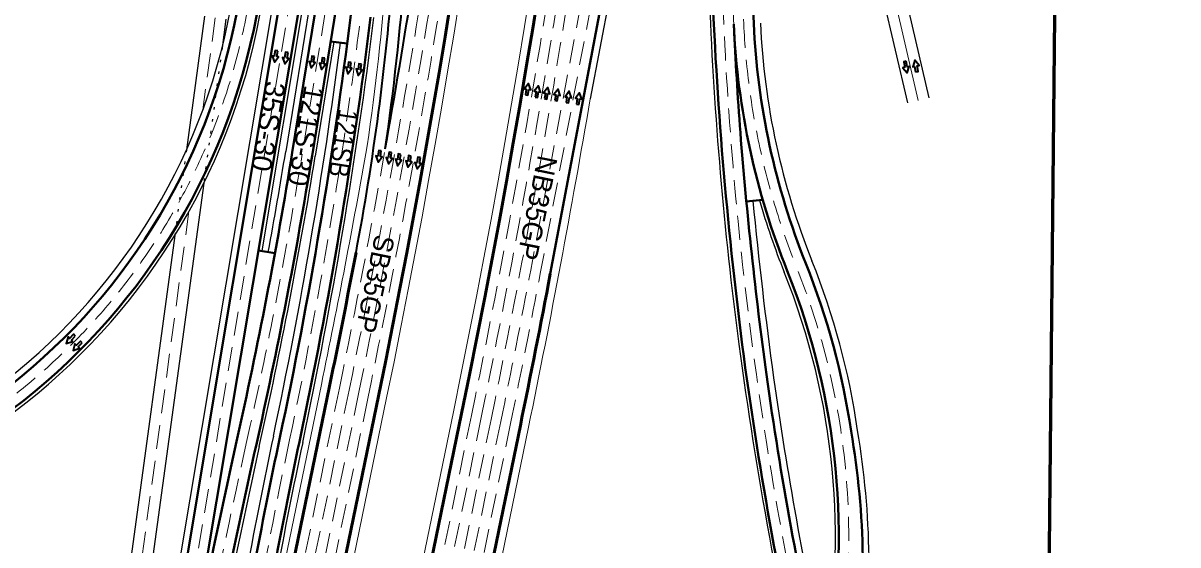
# Model space of a CAD drawing. Extents: x 2329387 to 2347382, y 6951580 to 6987999.
# Drawn here: x 2331366 to 2332753, y 6961173 to 6961800 of the extents above; entities that cross this region are included whole.
import ezdxf

# ---------------------------------------------------------------- set-up
doc = ezdxf.new("R2010")
doc.units = 0
doc.header["$LTSCALE"] = 9.6
doc.linetypes.add('DOTTED', pattern=[1.5, 0.3, -1.2])
doc.linetypes.add('MEDIUM_DASHED', pattern=[4.5, 3, -1.5])
for name, color, linetype, lineweight in [('26', 7, 'Continuous', 53), ('27', 7, 'Continuous', 40), ('28', 7, 'Continuous', 25), ('29', 7, 'DOTTED', 35), ('41', 7, 'Continuous', 35), ('50', 7, 'MEDIUM_DASHED', 13), ('62', 7, 'Continuous', 60), ('63', 7, 'Continuous', 25)]:
    doc.layers.add(name, color=color, linetype=linetype, lineweight=lineweight)
doc.layers.add('40', color=7, linetype='Continuous')

msp = doc.modelspace()

# ---------------------------------------------------------------- linework, layer by layer
at = {"layer": '26', "lineweight": 13}
for p, q in [((2331724.458, 6961366.169), (2331675.26, 6961127.125)), ((2331802.815, 6961350.042), (2331719.775, 6960946.564)), ((2331883.115, 6961333.431), (2331797.054, 6960915.276)), ((2331973.227, 6961314.885), (2331928.251, 6961096.357))]:
    msp.add_line(p, q, dxfattribs=at)
at = {"layer": '26'}
for p, q in [((2331734.252, 6961364.153), (2331685.095, 6961125.305)), ((2331734.252, 6961364.153), (2331685.095, 6961125.305)), ((2331793.021, 6961352.058), (2331710.29, 6960950.086)), ((2331892.91, 6961331.415), (2331806.417, 6960911.164)), ((2331963.432, 6961316.901), (2331918.456, 6961098.373))]:
    msp.add_line(p, q, dxfattribs=at)
for centre, radius, end in [((2320619.05, 6963651.709), 11510.156, 3.41668), ((2321018.843, 6963569.511), 11000, 2.99621), ((2321018.843, 6963569.511), 10940, 349.22683), ((2320619.05, 6963651.709), 11582.156, 349.28886)]:
    msp.add_arc(centre, radius, 348.37024, end, dxfattribs=at)
at = {"layer": '26', "lineweight": 13}
for centre, radius, end in [((2320619.05, 6963651.709), 11500.156, 3.35435), ((2321018.843, 6963569.511), 11010, 3.10741), ((2320619.05, 6963651.709), 11592.156, 350.35319), ((2321018.843, 6963569.511), 10930, 349.89956)]:
    msp.add_arc(centre, radius, 348.37024, end, dxfattribs=at)
at = {"layer": '27', "lineweight": 25}
for p, q in [((2331820.221, 6962498.609), (2331681.587, 6961645.951)), ((2331775.493, 6962479.35), (2331530.014, 6961010.115)), ((2331811.001, 6962473.417), (2331652.783, 6961526.455)), ((2332147.959, 6962241.392), (2332047.286, 6961709.162)), ((2331739.453, 6961777.528), (2331717.12, 6961640.174))]:
    msp.add_line(p, q, dxfattribs=at)
at = {"layer": '27'}
for p, q in [((2331828.117, 6962497.325), (2331689.483, 6961644.667)), ((2331783.384, 6962478.032), (2331537.705, 6961007.603)), ((2331807.056, 6962474.077), (2331560.779, 6961000.065)), ((2331819.966, 6962297.645), (2331713.172, 6961640.816)), ((2332140.099, 6962242.879), (2331999.406, 6961499.077)), ((2331735.484, 6961778.042), (2331755.318, 6961775.472)), ((2332254.609, 6961587.81), (2332234.696, 6961585.943)), ((2331668.564, 6961523.818), (2331648.838, 6961527.114))]:
    msp.add_line(p, q, dxfattribs=at)
for centre, radius, start, end in [((2339406.145, 6959556.474), 7976, 170.51466, 170.51466), ((2337955.315, 6962060.73), 5717.578, 174.34987, 182.61584), ((2330886.127, 6961953.624), 750.001, 266.08609, 350.71584), ((2330886.127, 6961953.624), 774.001, 266.08608, 350.71582), ((2337105.762, 6962041.019), 4915.948, 182.49984, 187.6536), ((2325828.855, 6962543.331), 5976, 348.01367, 352.95352), ((2325828.855, 6962543.331), 6000, 348.01367, 352.95352), ((2333124.25, 6961840.014), 905.473, 182.61584, 201.88176), ((2336798.354, 6962013.709), 4583.662, 182.68873, 184.31651), ((2333124.25, 6961840.014), 881.473, 182.61584, 201.88176), ((2337308.502, 6962068.63), 5096.522, 184.50052, 187.78871), ((2325767.265, 6962607.563), 5999.987, 347.39024, 350.76507), ((2325767.265, 6962607.563), 6023.987, 347.39024, 350.76507), ((2331488.314, 6961182.977), 857.473, 316.98269, 21.88176), ((2331488.314, 6961182.977), 881.473, 8.27518, 21.88176), ((2336798.354, 6962013.709), 4607.662, 187.82614, 193.20332), ((2336798.354, 6962013.709), 4583.662, 187.97272, 192.59319), ((2331429.011, 6961146.766), 945.765, 351.62744, 9.92921), ((2339406.145, 6959556.474), 7976, 167.39024, 169.57492), ((2339406.145, 6959556.474), 7952, 167.39024, 169.5982), ((2337567.201, 6960051.195), 6023.98, 168.01367, 171.10971), ((2337567.201, 6960051.195), 5999.98, 168.01367, 171.14683)]:
    msp.add_arc(centre, radius, start, end, dxfattribs=at)
at = {"layer": '27', "lineweight": 25}
for centre, radius, start, end in [((2330886.127, 6961953.624), 742.001, 266.08609, 350.71584), ((2330886.127, 6961953.624), 778.001, 266.08608, 350.71189), ((2336798.354, 6962013.709), 4611.662, 182.32731, 187.46451), ((2325828.855, 6962543.331), 6004, 348.01367, 352.95352), ((2333124.25, 6961840.014), 873.473, 182.61584, 201.88176), ((2325828.855, 6962543.331), 5968, 348.01367, 352.61764), ((2325767.265, 6962607.563), 6027.987, 347.39024, 350.76507), ((2325767.265, 6962607.563), 5991.987, 349.59262, 350.76507), ((2337545.513, 6962101.409), 5327.774, 185.54402, 187.84514), ((2333124.25, 6961840.014), 909.473, 196.12452, 201.88176), ((2331488.314, 6961182.977), 889.473, 8.27518, 21.88176), ((2331488.314, 6961182.977), 853.473, 316.98269, 21.88176), ((2337081.285, 6962065.532), 4898.95, 187.63559, 193.12349), ((2336798.354, 6962013.709), 4575.662, 188.03429, 192.35956), ((2337567.201, 6960051.195), 6031.98, 168.01367, 171.0974), ((2331388.291, 6961146.248), 993.984, 351.97584, 9.5406), ((2339406.145, 6959556.474), 7948, 167.39024, 169.60209), ((2337567.201, 6960051.195), 5995.98, 168.01367, 171.15332)]:
    msp.add_arc(centre, radius, start, end, dxfattribs=at)
at = {"layer": '28'}
for p, q in [((2332428.738, 6961704.35), (2332371.919, 6961949.587)), ((2332398.645, 6961949.425), (2332454.067, 6961710.219))]:
    msp.add_line(p, q, dxfattribs=at)
at = {"layer": '28', "lineweight": 13}
msp.add_arc((2328818.901, 6962085.355), 2991.998, 351.68506, 355.72896, dxfattribs=at)
at = {"layer": '29', "linetype": 'Continuous'}
for centre, radius, start, end in [((2321018.843, 6963569.511), 10952, 349.90135, 352.02498), ((2328818.901, 6962085.355), 2999.998, 349.22683, 355.72896), ((2328818.901, 6962085.355), 3013.998, 351.67854, 355.72896)]:
    msp.add_arc(centre, radius, start, end, dxfattribs=at)
at = {"layer": '41'}
for points in [[(2331671.923, 6961766.656), (2331668.961, 6961767.137), (2331667.87, 6961760.418), (2331665.464, 6961760.809), (2331668.04, 6961753.096), (2331672.924, 6961759.597), (2331670.832, 6961759.937)], [(2331684.341, 6961764.683), (2331681.379, 6961765.164), (2331680.288, 6961758.445), (2331677.882, 6961758.836), (2331680.458, 6961751.123), (2331685.342, 6961757.625), (2331683.25, 6961757.964)], [(2331716.082, 6961759.915), (2331713.12, 6961760.396), (2331712.029, 6961753.677), (2331709.623, 6961754.068), (2331712.199, 6961746.355), (2331717.083, 6961752.856), (2331714.991, 6961753.196)], [(2331728.5, 6961757.942), (2331725.538, 6961758.423), (2331724.447, 6961751.704), (2331722.041, 6961752.095), (2331724.617, 6961744.382), (2331729.501, 6961750.884), (2331727.409, 6961751.223)], [(2331760.083, 6961752.885), (2331757.121, 6961753.366), (2331756.03, 6961746.647), (2331753.624, 6961747.038), (2331756.2, 6961739.325), (2331761.084, 6961745.827), (2331758.992, 6961746.166)], [(2331772.501, 6961750.912), (2331769.539, 6961751.393), (2331768.448, 6961744.675), (2331766.042, 6961745.065), (2331768.618, 6961737.352), (2331773.502, 6961743.854), (2331771.41, 6961744.194)], [(2332426.905, 6961754.343), (2332423.961, 6961753.765), (2332425.271, 6961747.086), (2332422.879, 6961746.616), (2332427.973, 6961740.278), (2332430.295, 6961748.071), (2332428.215, 6961747.663)], [(2332438.219, 6961741.44), (2332441.163, 6961742.017), (2332439.853, 6961748.697), (2332442.245, 6961749.166), (2332437.15, 6961755.504), (2332434.828, 6961747.711), (2332436.908, 6961748.119)], [(2331969.402, 6961713.964), (2331972.364, 6961713.483), (2331973.455, 6961720.202), (2331975.861, 6961719.811), (2331973.285, 6961727.524), (2331968.401, 6961721.023), (2331970.493, 6961720.683)], [(2331981.187, 6961711.313), (2331984.149, 6961710.832), (2331985.24, 6961717.55), (2331987.646, 6961717.16), (2331985.07, 6961724.872), (2331980.186, 6961718.371), (2331982.278, 6961718.031)], [(2331992.339, 6961709.395), (2331995.301, 6961708.914), (2331996.392, 6961715.632), (2331998.798, 6961715.242), (2331996.222, 6961722.954), (2331991.338, 6961716.453), (2331993.43, 6961716.113)], [(2332004.757, 6961707.422), (2332007.719, 6961706.941), (2332008.81, 6961713.66), (2332011.216, 6961713.269), (2332008.64, 6961720.982), (2332003.756, 6961714.48), (2332005.848, 6961714.141)], [(2332018.287, 6961704.725), (2332021.249, 6961704.244), (2332022.34, 6961710.962), (2332024.746, 6961710.572), (2332022.17, 6961718.284), (2332017.286, 6961711.783), (2332019.378, 6961711.443)], [(2332030.705, 6961702.752), (2332033.667, 6961702.271), (2332034.758, 6961708.99), (2332037.163, 6961708.599), (2332034.588, 6961716.312), (2332029.704, 6961709.81), (2332031.796, 6961709.47)], [(2331796.341, 6961646.688), (2331793.38, 6961647.169), (2331792.289, 6961640.451), (2331789.883, 6961640.841), (2331792.459, 6961633.129), (2331797.343, 6961639.63), (2331795.25, 6961639.97)], [(2331808.759, 6961644.716), (2331805.797, 6961645.197), (2331804.706, 6961638.478), (2331802.301, 6961638.869), (2331804.876, 6961631.156), (2331809.76, 6961637.657), (2331807.668, 6961637.997)], [(2331819.715, 6961642.451), (2331816.753, 6961642.932), (2331815.662, 6961636.214), (2331813.257, 6961636.604), (2331815.833, 6961628.892), (2331820.717, 6961635.393), (2331818.624, 6961635.733)], [(2331832.133, 6961640.479), (2331829.171, 6961640.96), (2331828.08, 6961634.241), (2331825.674, 6961634.632), (2331828.25, 6961626.919), (2331833.134, 6961633.42), (2331831.042, 6961633.76)], [(2331843.286, 6961638.561), (2331840.324, 6961639.042), (2331839.233, 6961632.323), (2331836.827, 6961632.714), (2331839.403, 6961625.001), (2331844.287, 6961631.502), (2331842.195, 6961631.842)], [(2331428.833, 6961424.295), (2331426.665, 6961426.369), (2331421.959, 6961421.452), (2331420.198, 6961423.137), (2331417.95, 6961415.322), (2331425.659, 6961417.911), (2331424.127, 6961419.377)], [(2331437.107, 6961416.053), (2331434.939, 6961418.128), (2331430.233, 6961413.21), (2331428.472, 6961414.895), (2331426.224, 6961407.081), (2331433.933, 6961409.67), (2331432.401, 6961411.136)]]:
    msp.add_lwpolyline(points, close=True, dxfattribs=at)
at = {"layer": '50'}
for p, q in [((2331839.962, 6962495.399), (2331701.328, 6961642.742)), ((2331795.22, 6962476.054), (2331549.242, 6961003.834)), ((2332116.517, 6962247.339), (2331975.824, 6961503.538)), ((2332128.308, 6962245.109), (2331987.615, 6961501.307)), ((2331757.76, 6961359.315), (2331676.038, 6960962.247)), ((2331746.006, 6961361.734), (2331696.848, 6961122.886)), ((2331769.513, 6961356.896), (2331687.474, 6960958.284)), ((2331780.211, 6961349.347), (2331698.891, 6960954.23)), ((2331904.664, 6961328.996), (2331817.635, 6960906.143)), ((2331916.417, 6961326.577), (2331828.834, 6960901.027)), ((2331928.171, 6961324.158), (2331840.013, 6960895.817)), ((2331939.925, 6961321.739), (2331851.173, 6960890.511)), ((2331951.678, 6961319.32), (2331862.312, 6960885.108))]:
    msp.add_line(p, q, dxfattribs=at)
at = {"layer": '50', "linetype": 'Continuous'}
msp.add_line((2332441.403, 6961707.284), (2332384.584, 6961952.521), dxfattribs=at)
at = {"layer": '50'}
for centre, radius, start, end in [((2320619.05, 6963651.709), 11546.156, 348.37024, 3.62206), ((2320619.05, 6963651.709), 11534.156, 348.37024, 3.55667), ((2320619.05, 6963651.709), 11522.156, 348.37024, 3.48829), ((2321018.843, 6963569.511), 10988, 348.34293, 2.85027), ((2321018.843, 6963569.511), 10976, 348.37024, 2.68674), ((2321018.843, 6963569.511), 10964, 348.37024, 2.49877), ((2337955.315, 6962060.73), 5729.578, 174.34987, 182.61584), ((2330886.127, 6961953.624), 762.001, 266.08609, 350.71584), ((2336798.354, 6962013.709), 4595.662, 182.32731, 192.91301), ((2336798.354, 6962013.709), 4583.662, 182.32731, 182.68873), ((2325828.855, 6962543.331), 5988, 348.01367, 352.95352), ((2333124.25, 6961840.014), 893.473, 182.61584, 201.88176), ((2325767.265, 6962607.563), 6011.987, 347.39024, 350.76507), ((2321018.843, 6963569.511), 10952, 348.37024, 349.90135), ((2320619.05, 6963651.709), 11558.156, 348.37024, 349.28886), ((2320619.05, 6963651.709), 11570.156, 348.37024, 349.28886), ((2331488.314, 6961182.977), 869.473, 316.98269, 21.88176), ((2339406.145, 6959556.474), 7964, 167.39024, 169.58654), ((2337567.201, 6960051.195), 6011.98, 168.01367, 171.12823)]:
    msp.add_arc(centre, radius, start, end, dxfattribs=at)
at = {"layer": '62'}
msp.add_lwpolyline([(2332642.295, 6965522.154), (2332560.849, 6957416.973), (2330660.943, 6957436.065), (2330739.467, 6965250.394)], close=True, dxfattribs=at)
at = {"layer": '63'}
for p, q in [((2331584.072, 6961808.298), (2331562.27, 6961648.016)), ((2331609.834, 6961804.794), (2331605.162, 6961770.444)), ((2331583.039, 6961607.79), (2331502.947, 6961018.957)), ((2331548.281, 6961545.165), (2331477.824, 6961027.163))]:
    msp.add_line(p, q, dxfattribs=at)
at = {"layer": '63', "linetype": 'MEDIUM_DASHED', "lineweight": 13}
for p, q in [((2331596.953, 6961806.546), (2331581.886, 6961695.777)), ((2331565.355, 6961574.235), (2331490.386, 6961023.06))]:
    msp.add_line(p, q, dxfattribs=at)
at = {"layer": '63', "linetype": 'DOTTED'}
for p, q in [((2331605.162, 6961770.444), (2331583.039, 6961607.79)), ((2331562.27, 6961648.016), (2331548.281, 6961545.165))]:
    msp.add_line(p, q, dxfattribs=at)

# ---------------------------------------------------------------- texts
at = {"layer": '40'}
for s, rotation, width, p in [('35S-30', 260.43, 1.05, (2331657.76, 6961731.543)), ('121SB', 261.211, 0.85, (2331745.405, 6961698.095)), ('SB35GP', 258.419, 0.95, (2331789.125, 6961547.443))]:
    msp.add_text(s, height=24, rotation=rotation, dxfattribs=dict(at, width=width)).set_placement(p)
for s, rotation, p in [('121S-30', 260.321, (2331704.366, 6961726.4)), ('NB35GP', 258.419, (2331984.751, 6961642.693))]:
    msp.add_text(s, height=24, rotation=rotation, dxfattribs=at).set_placement(p)

doc.saveas('drawing.dxf')
